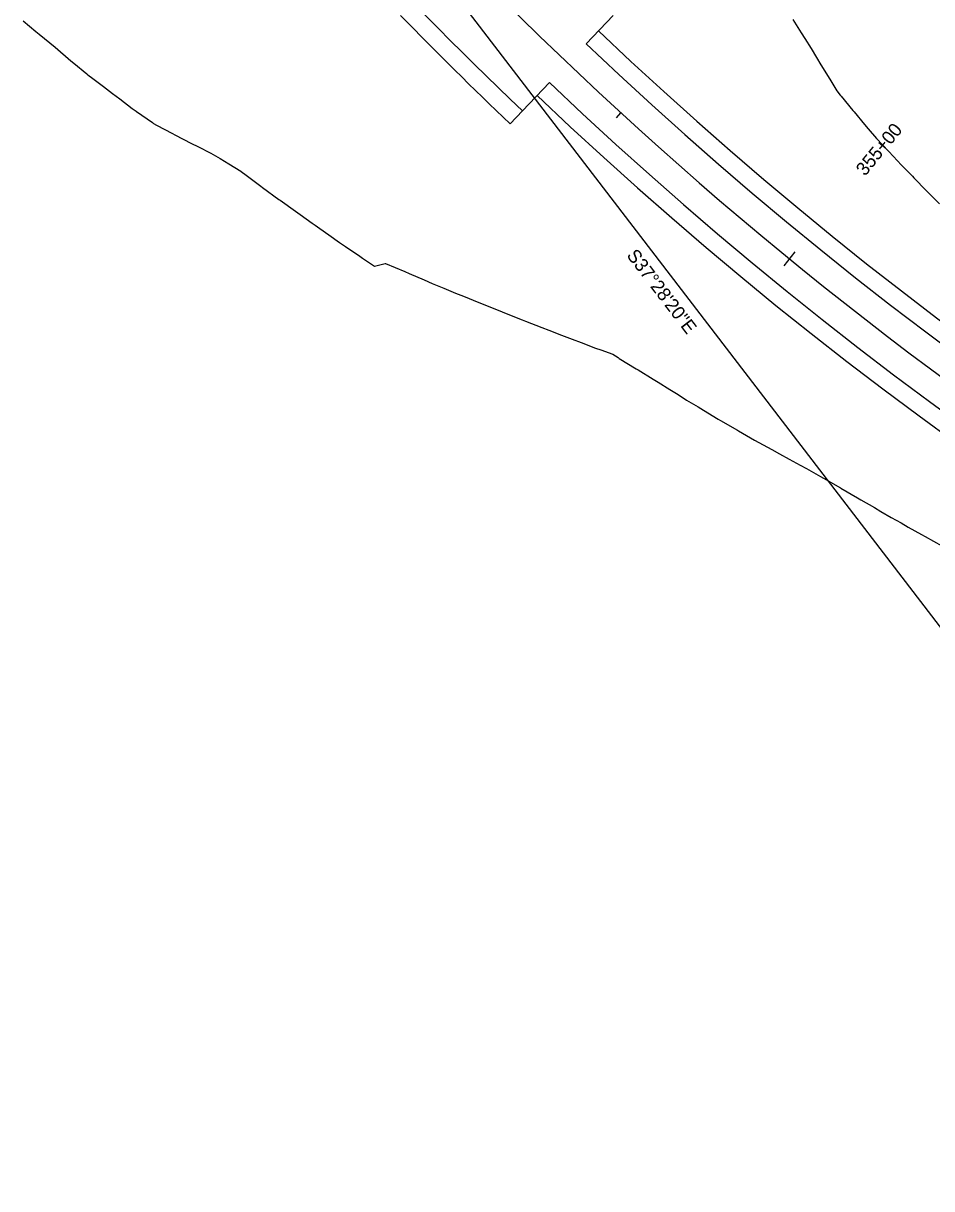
# Model space of a CAD drawing. Extents: x 881426 to 887360, y 1564404 to 1567430.
# Drawn here: x 884272 to 884680, y 1564489 to 1565012 of the extents above; entities that cross this region are included whole.
import ezdxf

# ---------------------------------------------------------------- set-up
doc = ezdxf.new("R2010")
doc.units = 0
for name, color, linetype in [('R_Horz Alg', 7, 'Continuous'), ('R_Horz Alg Annot', 7, 'Continuous'), ('R_Proposed Const Limits_Fill', 7, 'Continuous'), ('R_Proposed Road_Lane', 7, 'Continuous'), ('R_Proposed Road_Shoulder', 7, 'Continuous')]:
    doc.layers.add(name, color=color, linetype=linetype)

msp = doc.modelspace()

# ---------------------------------------------------------------- linework, layer by layer
at = {"layer": 'R_Horz Alg'}
msp.add_arc((885731.83, 1566270.57), 1762.95, 217.47218, 268.00892, dxfattribs=at)
at = {"layer": 'R_Horz Alg Annot'}
msp.add_line((884332.67, 1565198.04), (884838.93, 1564537.6), dxfattribs=at)
for points in [[(884538.07, 1564969.22), (884540.1, 1564971.43)], [(884618.2, 1564909.05), (884613.14, 1564902.86)]]:
    msp.add_lwpolyline(points, dxfattribs=at)
at = {"layer": 'R_Proposed Const Limits_Fill'}
for points in [[(884272.03, 1565012.72), (884277.71, 1565007.89), (884279.21, 1565006.79), (884286.31, 1565000.91), (884286.36, 1565000.85), (884293.34, 1564994.78), (884294.64, 1564993.71), (884300.53, 1564988.92), (884300.98, 1564988.56), (884303.27, 1564986.81), (884307.94, 1564983.26), (884312.11, 1564980.12), (884315.39, 1564977.67), (884320.89, 1564973.41), (884322.61, 1564972.18), (884322.79, 1564972.06), (884330, 1564967.03), (884330.47, 1564966.72), (884331.76, 1564965.86), (884338.92, 1564962.14), (884340.04, 1564961.57), (884347.52, 1564957.74), (884350.27, 1564956.34), (884356.13, 1564953.4), (884360.32, 1564951), (884364.23, 1564948.59), (884369.55, 1564945.33), (884369.79, 1564945.15), (884372, 1564943.5), (884378.51, 1564938.61), (884379.33, 1564938), (884386.73, 1564932.6), (884387.32, 1564932.18), (884394.06, 1564927.33), (884394.17, 1564927.25), (884396.16, 1564925.82), (884401.62, 1564921.93), (884402.92, 1564921), (884405.03, 1564919.51), (884409.09, 1564916.65), (884413.94, 1564913.26), (884416.62, 1564911.46), (884422.94, 1564907.14), (884424.16, 1564906.3), (884429.58, 1564902.61), (884434.31, 1564903.9), (884434.55, 1564903.8), (884443.2, 1564900.24), (884445.09, 1564899.41), (884451.92, 1564896.45), (884455.47, 1564894.92), (884460.66, 1564892.71), (884465.94, 1564890.59), (884469.47, 1564889.11), (884476.37, 1564886.27), (884478.26, 1564885.52), (884486.9, 1564882.14), (884487.11, 1564882.05), (884495.87, 1564878.53), (884497.33, 1564877.95), (884504.71, 1564875.13), (884507.82, 1564873.91), (884513.46, 1564871.69), (884518.28, 1564869.9), (884522.29, 1564868.39), (884528.72, 1564865.92), (884531.06, 1564865.06), (884536.5, 1564863.09), (884538.83, 1564861.63), (884539.4, 1564861.27), (884546.96, 1564856.6), (884547.83, 1564856.07), (884554.53, 1564851.95), (884556.83, 1564850.53), (884562.13, 1564847.35), (884565.87, 1564845.07), (884569.55, 1564842.54), (884574.78, 1564839.48), (884577.21, 1564838.07), (884583.75, 1564833.98), (884584.73, 1564833.42), (884592.45, 1564829.05), (884592.93, 1564828.77), (884600.08, 1564824.59), (884602.04, 1564823.51), (884607.85, 1564820.33), (884611.29, 1564818.45), (884615.61, 1564816.07), (884620.53, 1564813.4), (884623.36, 1564811.82), (884629.69, 1564808.29), (884631.06, 1564807.52), (884638.68, 1564803.14), (884638.77, 1564803.09), (884646.23, 1564798.68), (884647.75, 1564797.79), (884653.81, 1564794.28), (884656.78, 1564792.56), (884661.41, 1564789.91), (884665.83, 1564787.4), (884669.02, 1564785.58), (884674.92, 1564782.29), (884676.67, 1564781.31), (884684.01, 1564777.22)], [(884617.27, 1565013.26), (884620.97, 1565007.34), (884622.55, 1565004.82), (884625.44, 1565000.26), (884627.81, 1564996.32), (884629.8, 1564993.03), (884633.05, 1564987.73), (884634.23, 1564985.82), (884636.94, 1564981.36), (884638.52, 1564979.36), (884638.91, 1564978.88), (884644.13, 1564972.55), (884644.73, 1564971.83), (884649.4, 1564966.25), (884650.99, 1564964.33), (884654.71, 1564959.99), (884657.45, 1564957.04), (884660.28, 1564954.02), (884664.12, 1564949.97), (884665.91, 1564948.11), (884670.85, 1564942.96), (884671.57, 1564942.22), (884677.27, 1564936.37), (884677.63, 1564936), (884683.02, 1564930.56)]]:
    msp.add_lwpolyline(points, dxfattribs=at)
at = {"layer": 'R_Proposed Road_Lane'}
for p, q in [((884536.63, 1565015.05), (884524.56, 1565002.38)), ((884495.95, 1564972.32), (884508.01, 1564984.99))]:
    msp.add_line(p, q, dxfattribs=at)
for radius, start, end in [(1792.45, 218.69432, 226.40988), (1750.95, 226.40988, 268.00892), (1774.95, 226.40988, 268.00892)]:
    msp.add_arc((885731.83, 1566270.57), radius, start, end, dxfattribs=at)
at = {"layer": 'R_Proposed Road_Shoulder'}
msp.add_line((884490.43, 1564966.52), (884495.95, 1564972.32), dxfattribs=at)
for radius, start, end in [(1800.45, 224.2106, 226.40988), (1742.95, 226.40988, 268.00892), (1782.95, 226.40988, 268.00892)]:
    msp.add_arc((885731.83, 1566270.57), radius, start, end, dxfattribs=at)

# ---------------------------------------------------------------- texts
at = {"layer": 'R_Horz Alg Annot'}
for s, rotation, p in [('355+00', 50.7193, (884649.65, 1564942.76)), ('S37%%d28\'20"E', 307.4722, (884542.4, 1564907.4))]:
    msp.add_text(s, height=6, rotation=rotation, dxfattribs=at).set_placement(p)

doc.saveas('drawing.dxf')
